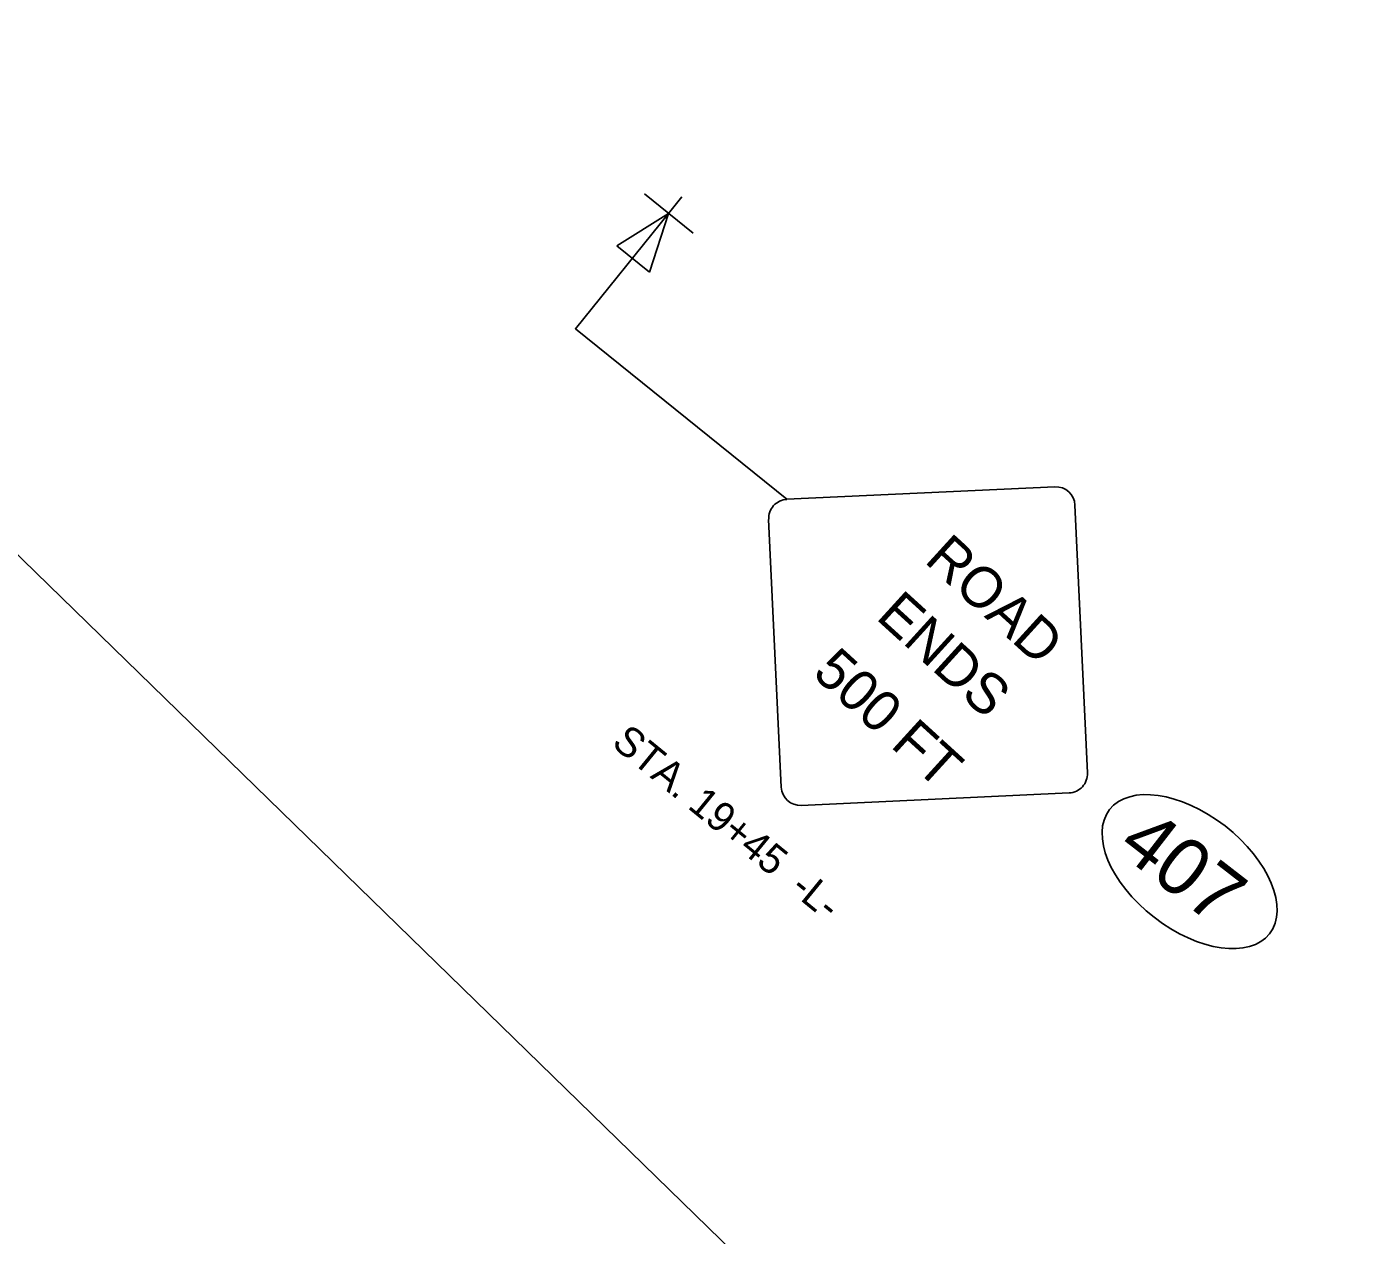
# Model space of a CAD drawing. Extents: x 1487362 to 2061618, y 497428 to 671257.
# Drawn here: x 1488478.5 to 1488624.6, y 498740.2 to 498871.7 of the extents above; entities that cross this region are included whole.
import ezdxf

# ---------------------------------------------------------------- set-up
doc = ezdxf.new("R2010")
doc.units = 0
for name, color, linetype in [('Prop Sign E', 7, 'Continuous'), ('Prop Sign E Ahead Plaque CELL', 7, 'Continuous'), ('Prop Support One', 7, 'Continuous'), ('Scratch_Level_1', 7, 'Continuous'), ('Text', 7, 'Continuous')]:
    doc.layers.add(name, color=color, linetype=linetype)

msp = doc.modelspace()

# ---------------------------------------------------------------- linework, layer by layer
at = {"layer": 'Prop Sign E'}
for p, q in [((1488590.34, 498821.65), (1488561.19, 498820.29)), ((1488593.88, 498790.52), (1488592.52, 498819.67)), ((1488559.2, 498818.11), (1488560.57, 498788.96)), ((1488562.74, 498786.98), (1488591.9, 498788.34))]:
    msp.add_line(p, q, dxfattribs=at)
for centre, start, end in [((1488590.44, 498819.57), 2.6767, 92.6767), ((1488561.28, 498818.21), 92.6767, 182.6767), ((1488591.8, 498790.42), 272.6767, 2.6767), ((1488562.65, 498789.06), 182.6767, 272.6767)]:
    msp.add_arc(centre, 2.08, start, end, dxfattribs=at)
at = {"layer": 'Prop Sign E Ahead Plaque CELL'}
msp.add_ellipse((1488604.99, 498779.78), major_axis=(-8.7, 6.75), ratio=0.571429, dxfattribs=at)
at = {"layer": 'Prop Support One'}
for p, q in [((1488550.97, 498849.25), (1488545.68, 498853.52)), ((1488548.3, 498851.4), (1488549.76, 498853.21)), ((1488542.67, 498847.86), (1488548.3, 498851.4)), ((1488548.3, 498851.4), (1488546.23, 498844.99)), ((1488546.23, 498844.99), (1488542.67, 498847.86))]:
    msp.add_line(p, q, dxfattribs=at)
msp.add_lwpolyline([(1488548.3, 498851.4), (1488538.18, 498838.85), (1488561.19, 498820.29)], dxfattribs=at)
at = {"layer": 'Scratch_Level_1'}
msp.add_line((1488338.15, 498950), (1488624.64, 498670.85), dxfattribs=at)

# ---------------------------------------------------------------- texts
at = {"layer": 'Prop Sign E'}
for s, p in [('ROAD', (1488576.02, 498813.52)), ('ENDS', (1488570.75, 498807.35)), ('500 FT', (1488563.82, 498801.19))]:
    msp.add_text(s, height=4.427, rotation=317.6767, dxfattribs=at).set_placement(p)
at = {"layer": 'Prop Sign E Ahead Plaque CELL'}
msp.add_text('407', height=6.218, rotation=322.2164, dxfattribs=at).set_placement((1488596.92, 498782.11))
at = {"layer": 'Text'}
msp.add_text('STA. 19+45  -L-', height=3.2, rotation=320.7424, dxfattribs=at).set_placement((1488541.98, 498793.54))

doc.saveas('drawing.dxf')
